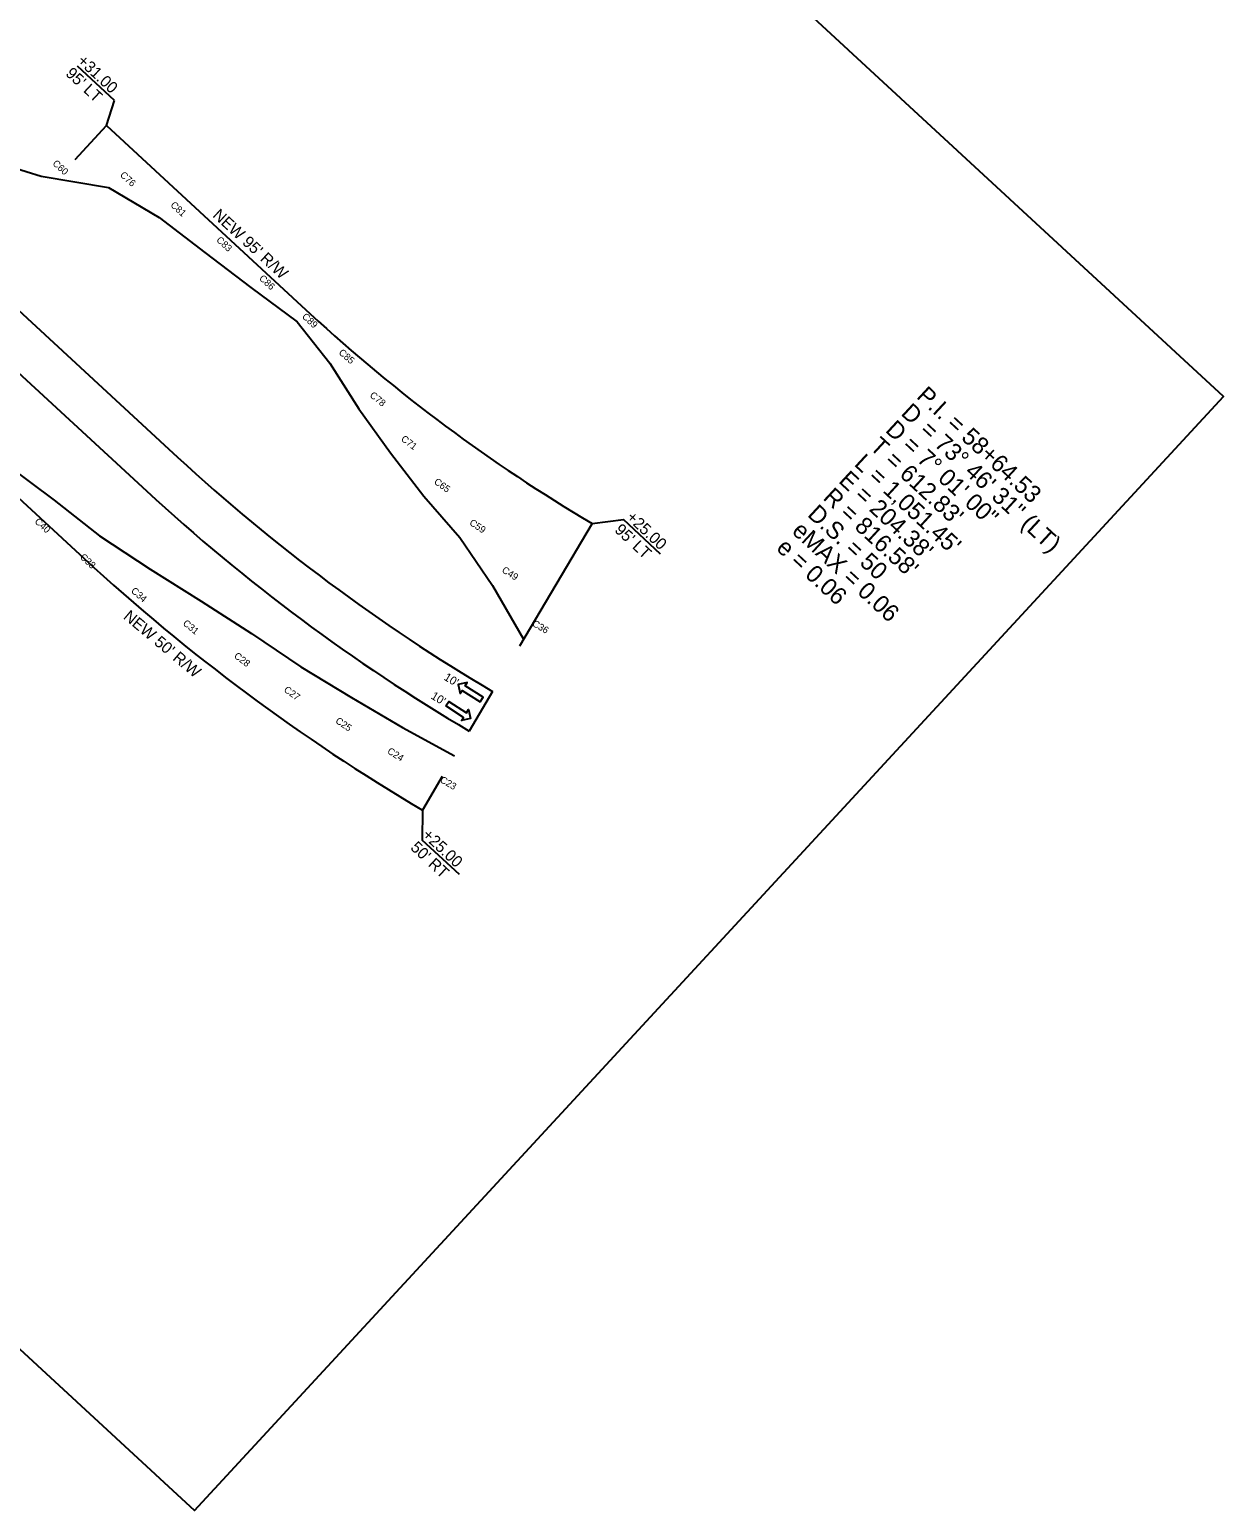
# Model space of a CAD drawing. Extents: x 1877044 to 1878285, y 1204828 to 1206046.
# Drawn here: x 1877765 to 1878285, y 1204828 to 1205473 of the extents above; entities that cross this region are included whole.
import ezdxf

# ---------------------------------------------------------------- set-up
doc = ezdxf.new("R2010")
doc.units = 0
for name, color, linetype in [('RD_HC_Data', 7, 'Continuous'), ('RD_PD_CstnLmt', 7, 'Continuous'), ('RD_PD_CstnLmt_TX', 7, 'Continuous'), ('RD_PD_Final_TrvlWay', 7, 'Continuous'), ('RD_PD_Final_TX', 7, 'Continuous'), ('RD_PD_RW', 7, 'Continuous'), ('RD_PD_RW_TX', 7, 'Continuous'), ('RD_SHT_TX', 7, 'Continuous'), ('RD_Sketch2', 7, 'Continuous')]:
    doc.layers.add(name, color=color, linetype=linetype)

msp = doc.modelspace()

# ---------------------------------------------------------------- linework, layer by layer
at = {"layer": 'RD_PD_CstnLmt'}
for p, q in [((1877743.65, 1205416.9), (1877770.21, 1205408.81)), ((1877770.21, 1205408.81), (1877799.59, 1205403.78)), ((1877799.59, 1205403.78), (1877821.55, 1205390.71)), ((1877821.55, 1205390.71), (1877841.51, 1205375.48)), ((1877841.51, 1205375.48), (1877861.57, 1205360.34)), ((1877861.57, 1205360.34), (1877881.72, 1205345.32)), ((1877881.72, 1205345.32), (1877895.93, 1205327.42)), ((1877895.93, 1205327.42), (1877908.57, 1205307.51)), ((1877908.57, 1205307.51), (1877922.33, 1205288.3)), ((1877922.33, 1205288.3), (1877936.88, 1205269.47)), ((1877755.86, 1205282.72), (1877775.99, 1205267.67)), ((1877775.99, 1205267.67), (1877795.71, 1205252.18)), ((1877936.88, 1205269.47), (1877952.46, 1205251.44)), ((1877795.71, 1205252.18), (1877817.66, 1205237.66)), ((1877952.46, 1205251.44), (1877966.74, 1205230.64)), ((1877817.66, 1205237.66), (1877839.92, 1205223.73)), ((1877966.74, 1205230.64), (1877980.15, 1205207.17)), ((1877839.92, 1205223.73), (1877861.85, 1205209.71)), ((1877861.85, 1205209.71), (1877883.24, 1205195.17)), ((1877883.24, 1205195.17), (1877905.36, 1205181.79)), ((1877905.36, 1205181.79), (1877927.59, 1205168.75)), ((1877927.59, 1205168.75), (1877950.16, 1205156.38))]:
    msp.add_line(p, q, dxfattribs=at)
at = {"layer": 'RD_PD_Final_TrvlWay'}
for p, q in [((1877424.35, 1205660.73), (1877829.65, 1205286.43)), ((1877410.78, 1205646.04), (1877816.08, 1205271.74)), ((1877966.75, 1205184.45), (1877956.56, 1205167.24))]:
    msp.add_line(p, q, dxfattribs=at)
for radius, end in [(806.58, 239.43728), (826.58, 239.43604)]:
    msp.add_arc((1878376.88, 1205878.98), radius, 227.27672, end, dxfattribs=at)
at = {"layer": 'RD_PD_Final_TX'}
for points in [[(1877961.32, 1205180.02), (1877962.6, 1205182.05), (1877954.84, 1205186.94), (1877955.71, 1205188.32), (1877951.8, 1205187.43), (1877952.69, 1205183.53), (1877953.56, 1205184.91)], [(1877946.4, 1205178.14), (1877947.69, 1205180.16), (1877955.42, 1205175.22), (1877956.29, 1205176.59), (1877957.15, 1205172.68), (1877953.24, 1205171.82), (1877954.12, 1205173.19)]]:
    msp.add_lwpolyline(points, close=True, dxfattribs=at)
at = {"layer": 'RD_PD_RW'}
for p, q in [((1877785.08, 1205416.07), (1877798.65, 1205430.77)), ((1877798.65, 1205430.77), (1877887.32, 1205348.88)), ((1877714.23, 1205311.35), (1877788.94, 1205242.35)), ((1878010.04, 1205257.6), (1877978.46, 1205204.25)), ((1877944.85, 1205147.44), (1877936.19, 1205132.81))]:
    msp.add_line(p, q, dxfattribs=at)
for radius, end in [(721.58, 239.44329), (866.58, 239.43374)]:
    msp.add_arc((1878376.88, 1205878.98), radius, 227.27672, end, dxfattribs=at)
at = {"layer": 'RD_PD_RW_TX'}
for p, q in [((1877802.21, 1205441.73), (1877786.03, 1205456.66)), ((1877798.65, 1205430.77), (1877802.21, 1205441.73)), ((1878010.04, 1205257.6), (1878023.65, 1205259.25)), ((1878039.78, 1205244.28), (1878023.65, 1205259.25)), ((1877936.19, 1205132.81), (1877936.15, 1205119.75)), ((1877952.29, 1205104.78), (1877936.15, 1205119.75))]:
    msp.add_line(p, q, dxfattribs=at)
at = {"layer": 'RD_Sketch2'}
msp.add_lwpolyline([(1877043.62, 1205560.73), (1877837.06, 1204828.03), (1878284.82, 1205312.91), (1877491.38, 1206045.61)], close=True, dxfattribs=at)

# ---------------------------------------------------------------- texts
at = {"layer": 'RD_HC_Data'}
for s, p in [('P.I. = 58+64.53', (1878150.87, 1205312.43)), ('D', (1878144.09, 1205305.09)), ('D = 7%%d 01\' 00"', (1878137.3, 1205297.74)), ('    = 73%%d 46\' 31" (LT)', (1878144.09, 1205305.09)), ("T = 612.83'", (1878130.52, 1205290.39)), ("L = 1,051.45'", (1878123.73, 1205283.05)), ("E = 204.38'", (1878116.95, 1205275.7)), ("R = 816.58'", (1878110.16, 1205268.35)), ('D.S. = 50', (1878103.38, 1205261.01)), ('eMAX = 0.06', (1878096.6, 1205253.66)), ('e = 0.06', (1878089.81, 1205246.31))]:
    msp.add_text(s, height=7.5, rotation=317.27908, dxfattribs=at).set_placement(p)
at = {"layer": 'RD_PD_CstnLmt_TX'}
for s, rotation, p in [('C60', 317.27672, (1877774.96, 1205413.95)), ('C76', 317.27672, (1877804.34, 1205408.92)), ('C81', 317.27672, (1877826.3, 1205395.85)), ('C83', 317.27672, (1877846.26, 1205380.62)), ('C86', 317.27672, (1877864.88, 1205363.93)), ('C89', 317.27672, (1877883.56, 1205347.3)), ('C85', 318.91185, (1877899.5, 1205331.58)), ('C78', 320.66598, (1877913.01, 1205312.92)), ('C71', 322.42012, (1877926.6, 1205293.85)), ('C65', 324.17425, (1877940.97, 1205275.15)), ('C40', 317.27672, (1877767.17, 1205258.12)), ('C59', 325.92838, (1877956.38, 1205257.24)), ('C38', 317.27672, (1877786.89, 1205242.63)), ('C49', 327.68252, (1877970.49, 1205236.56)), ('C34', 318.91185, (1877809.12, 1205227.86)), ('C31', 320.66598, (1877831.68, 1205213.68)), ('C36', 329.43665, (1877983.71, 1205213.19)), ('C28', 322.42012, (1877853.92, 1205199.41)), ('C27', 324.17425, (1877875.63, 1205184.63)), ('C25', 325.92838, (1877898.07, 1205171.03)), ('C24', 327.68252, (1877920.64, 1205157.76)), ('C23', 329.43665, (1877943.55, 1205145.19))]:
    msp.add_text(s, height=3, rotation=rotation, dxfattribs=at).set_placement(p)
at = {"layer": 'RD_PD_RW_TX'}
for s, rotation, p in [('+31.00', 317.07125, (1877785.65, 1205458.45)), ("95' LT", 317.07125, (1877780.54, 1205452.96)), ("NEW 95' R/W", 317.51885, (1877844.6, 1205391.29)), ('+25.00', 316.93656, (1878024.62, 1205259.8)), ("95' LT", 316.93656, (1878019.5, 1205254.32)), ("NEW 50' R/W", 320.02497, (1877805.71, 1205216.47)), ("50' RT", 316.93656, (1877930.66, 1205116.06)), ('+25.00', 316.93656, (1877935.78, 1205121.54))]:
    msp.add_text(s, height=5, rotation=rotation, dxfattribs=at).set_placement(p)
at = {"layer": 'RD_SHT_TX'}
for p in [(1877945.22, 1205189.77), (1877939.58, 1205181.59)]:
    msp.add_text("10'", height=3.6, rotation=328.67727, dxfattribs=at).set_placement(p)

doc.saveas('drawing.dxf')
